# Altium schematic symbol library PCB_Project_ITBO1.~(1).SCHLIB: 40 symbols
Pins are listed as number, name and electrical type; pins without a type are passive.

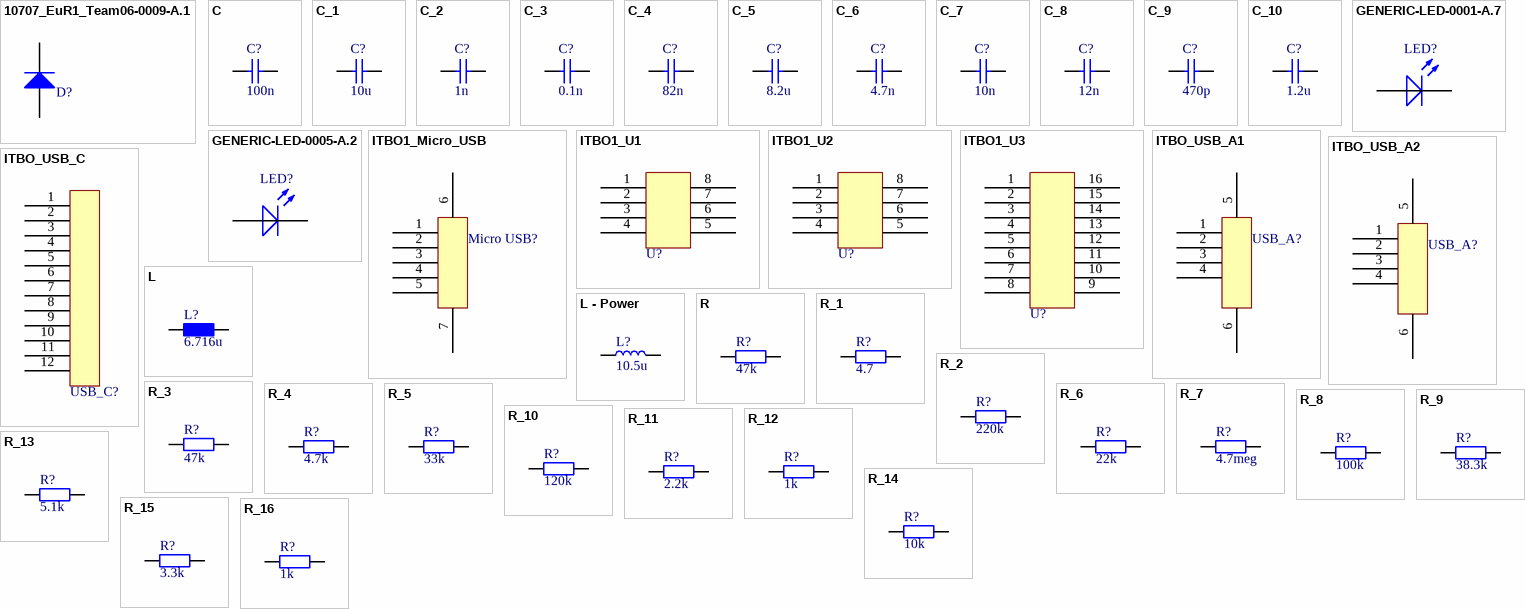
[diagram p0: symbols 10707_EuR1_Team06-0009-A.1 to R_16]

## 10707_EuR1_Team06-0009-A.1
designator D?, comment 1N4148W-7-F  (value not drawn)
Fast Switching Diode, 100 V, 2 A, 300 mA; Manufacturer: Diodes Incorporated
footprint DIODES_SOD123_2_H
pins: 1 K, 2 A

## C
designator C?, comment 100n
Capacitor; #Manufacturer: Generic Components; #Publisher: Dr. A. Heinzelmann; #Class: Passive; Initial Voltage: 0V
footprint 0805
simulation model CAP (Capacitor)
footprint 1210
footprint 0603
footprint CC-Type-B-3528 (Chip Capacitor; Body 3.5 x 2.8 mm (LxW typ))
footprint 1206 (SMD Chip 1206)
footprint 0402 (SMD Chip 0402)
footprint 1812 (Chip Capacitor; Body 4.5 x 3.2 mm (LxW typ))
footprint 0402 - R (SMD Chip 0402 - Reflow)
footprint 0603 - R (SMD Chip 0603 - Reflow)
footprint 0805 - R (SMD Chip 0805 - Reflow)
footprint 1206 - R (SMD Chip 1206 - Reflow)
pins: 1, 2

## C_1
designator C?, comment 10u
Capacitor; #Manufacturer: Generic Components; #Publisher: Dr. A. Heinzelmann; #Class: Passive; Initial Voltage: 0V
footprint 0805
simulation model CAP (Capacitor)
footprint 1210
footprint 0603
footprint CC-Type-B-3528 (Chip Capacitor; Body 3.5 x 2.8 mm (LxW typ))
footprint 1206 (SMD Chip 1206)
footprint 0402 (SMD Chip 0402)
footprint 1812 (Chip Capacitor; Body 4.5 x 3.2 mm (LxW typ))
footprint 0402 - R (SMD Chip 0402 - Reflow)
footprint 0603 - R (SMD Chip 0603 - Reflow)
footprint 0805 - R (SMD Chip 0805 - Reflow)
footprint 1206 - R (SMD Chip 1206 - Reflow)
pins: 1, 2

## C_2
designator C?, comment 1n
Capacitor; #Manufacturer: Generic Components; #Publisher: Dr. A. Heinzelmann; #Class: Passive; Initial Voltage: 0V
footprint 0805
simulation model CAP (Capacitor)
footprint 1210
footprint 0603
footprint CC-Type-B-3528 (Chip Capacitor; Body 3.5 x 2.8 mm (LxW typ))
footprint 1206 (SMD Chip 1206)
footprint 0402 (SMD Chip 0402)
footprint 1812 (Chip Capacitor; Body 4.5 x 3.2 mm (LxW typ))
footprint 0402 - R (SMD Chip 0402 - Reflow)
footprint 0603 - R (SMD Chip 0603 - Reflow)
footprint 0805 - R (SMD Chip 0805 - Reflow)
footprint 1206 - R (SMD Chip 1206 - Reflow)
pins: 1, 2

## C_3
designator C?, comment 0.1n
Capacitor; #Manufacturer: Generic Components; #Publisher: Dr. A. Heinzelmann; #Class: Passive; Initial Voltage: 0V
footprint 0805
simulation model CAP (Capacitor)
footprint 1210
footprint 0603
footprint CC-Type-B-3528 (Chip Capacitor; Body 3.5 x 2.8 mm (LxW typ))
footprint 1206 (SMD Chip 1206)
footprint 0402 (SMD Chip 0402)
footprint 1812 (Chip Capacitor; Body 4.5 x 3.2 mm (LxW typ))
footprint 0402 - R (SMD Chip 0402 - Reflow)
footprint 0603 - R (SMD Chip 0603 - Reflow)
footprint 0805 - R (SMD Chip 0805 - Reflow)
footprint 1206 - R (SMD Chip 1206 - Reflow)
pins: 1, 2

## C_4
designator C?, comment 82n
Capacitor; #Manufacturer: Generic Components; #Publisher: Dr. A. Heinzelmann; #Class: Passive; Initial Voltage: 0V
footprint 0805
simulation model CAP (Capacitor)
footprint 1210
footprint 0603
footprint CC-Type-B-3528 (Chip Capacitor; Body 3.5 x 2.8 mm (LxW typ))
footprint 1206 (SMD Chip 1206)
footprint 0402 (SMD Chip 0402)
footprint 1812 (Chip Capacitor; Body 4.5 x 3.2 mm (LxW typ))
footprint 0402 - R (SMD Chip 0402 - Reflow)
footprint 0603 - R (SMD Chip 0603 - Reflow)
footprint 0805 - R (SMD Chip 0805 - Reflow)
footprint 1206 - R (SMD Chip 1206 - Reflow)
pins: 1, 2

## C_5
designator C?, comment 8.2u
Capacitor; #Manufacturer: Generic Components; #Publisher: Dr. A. Heinzelmann; #Class: Passive; Initial Voltage: 0V
footprint 0805
simulation model CAP (Capacitor)
footprint 1210
footprint 0603
footprint CC-Type-B-3528 (Chip Capacitor; Body 3.5 x 2.8 mm (LxW typ))
footprint 1206 (SMD Chip 1206)
footprint 0402 (SMD Chip 0402)
footprint 1812 (Chip Capacitor; Body 4.5 x 3.2 mm (LxW typ))
footprint 0402 - R (SMD Chip 0402 - Reflow)
footprint 0603 - R (SMD Chip 0603 - Reflow)
footprint 0805 - R (SMD Chip 0805 - Reflow)
footprint 1206 - R (SMD Chip 1206 - Reflow)
pins: 1, 2

## C_6
designator C?, comment 4.7n
Capacitor; #Manufacturer: Generic Components; #Publisher: Dr. A. Heinzelmann; #Class: Passive; Initial Voltage: 0V
footprint 0805
simulation model CAP (Capacitor)
footprint 1210
footprint 0603
footprint CC-Type-B-3528 (Chip Capacitor; Body 3.5 x 2.8 mm (LxW typ))
footprint 1206 (SMD Chip 1206)
footprint 0402 (SMD Chip 0402)
footprint 1812 (Chip Capacitor; Body 4.5 x 3.2 mm (LxW typ))
footprint 0402 - R (SMD Chip 0402 - Reflow)
footprint 0603 - R (SMD Chip 0603 - Reflow)
footprint 0805 - R (SMD Chip 0805 - Reflow)
footprint 1206 - R (SMD Chip 1206 - Reflow)
pins: 1, 2

## C_7
designator C?, comment 10n
Capacitor; #Manufacturer: Generic Components; #Publisher: Dr. A. Heinzelmann; #Class: Passive; Initial Voltage: 0V
footprint 0805
simulation model CAP (Capacitor)
footprint 1210
footprint 0603
footprint CC-Type-B-3528 (Chip Capacitor; Body 3.5 x 2.8 mm (LxW typ))
footprint 1206 (SMD Chip 1206)
footprint 0402 (SMD Chip 0402)
footprint 1812 (Chip Capacitor; Body 4.5 x 3.2 mm (LxW typ))
footprint 0402 - R (SMD Chip 0402 - Reflow)
footprint 0603 - R (SMD Chip 0603 - Reflow)
footprint 0805 - R (SMD Chip 0805 - Reflow)
footprint 1206 - R (SMD Chip 1206 - Reflow)
pins: 1, 2

## C_8
designator C?, comment 12n
Capacitor; #Manufacturer: Generic Components; #Publisher: Dr. A. Heinzelmann; #Class: Passive; Initial Voltage: 0V
footprint 0805
simulation model CAP (Capacitor)
footprint 1210
footprint 0603
footprint CC-Type-B-3528 (Chip Capacitor; Body 3.5 x 2.8 mm (LxW typ))
footprint 1206 (SMD Chip 1206)
footprint 0402 (SMD Chip 0402)
footprint 1812 (Chip Capacitor; Body 4.5 x 3.2 mm (LxW typ))
footprint 0402 - R (SMD Chip 0402 - Reflow)
footprint 0603 - R (SMD Chip 0603 - Reflow)
footprint 0805 - R (SMD Chip 0805 - Reflow)
footprint 1206 - R (SMD Chip 1206 - Reflow)
pins: 1, 2

## C_9
designator C?, comment 470p
Capacitor; #Manufacturer: Generic Components; #Publisher: Dr. A. Heinzelmann; #Class: Passive; Initial Voltage: 0V
footprint 0805
simulation model CAP (Capacitor)
footprint 1210
footprint 0603
footprint CC-Type-B-3528 (Chip Capacitor; Body 3.5 x 2.8 mm (LxW typ))
footprint 1206 (SMD Chip 1206)
footprint 0402 (SMD Chip 0402)
footprint 1812 (Chip Capacitor; Body 4.5 x 3.2 mm (LxW typ))
footprint 0402 - R (SMD Chip 0402 - Reflow)
footprint 0603 - R (SMD Chip 0603 - Reflow)
footprint 0805 - R (SMD Chip 0805 - Reflow)
footprint 1206 - R (SMD Chip 1206 - Reflow)
pins: 1, 2

## C_10
designator C?, comment 1.2u
Capacitor; #Manufacturer: Generic Components; #Publisher: Dr. A. Heinzelmann; #Class: Passive; Initial Voltage: 0V
footprint 0805
simulation model CAP (Capacitor)
footprint 1210
footprint 0603
footprint CC-Type-B-3528 (Chip Capacitor; Body 3.5 x 2.8 mm (LxW typ))
footprint 1206 (SMD Chip 1206)
footprint 0402 (SMD Chip 0402)
footprint 1812 (Chip Capacitor; Body 4.5 x 3.2 mm (LxW typ))
footprint 0402 - R (SMD Chip 0402 - Reflow)
footprint 0603 - R (SMD Chip 0603 - Reflow)
footprint 0805 - R (SMD Chip 0805 - Reflow)
footprint 1206 - R (SMD Chip 1206 - Reflow)
pins: 1, 2

## GENERIC-LED-0001-A.7
designator LED?, comment tbd  (value not drawn)
LED red; Manufacturer: generic; #ClassSub: LEDs; #Class: Generic-Components
footprint LED-RED-0603[1608]  - RFL (SMD Chip 0603 - LED RED - RFL)
footprint LED-RED-0603[1608] (SMD Chip 0603 - LED RED)
footprint LED-RED-0805[2012] (SMD Chip 0805 - LED RED)
footprint LED-RED-0805[2012]  - RFL (SMD Chip 0805 - LED RED - RFL)
pins: 1 K, 2 A

## GENERIC-LED-0005-A.2
designator LED?, comment tbd  (value not drawn)
LED blue; Manufacturer: generic; #ClassSub: LEDs; #Class: Generic-Components
footprint LED-BLUE-0603[1608]  - RFL (SMD Chip 0603 - LED BLUE - RFL)
footprint LED-BLUE-0805[2012]  - RFL (SMD Chip 0805 - LED BLUE - RFL)
footprint LED-BLUE-0805[2012] (SMD Chip 0805 - LED BLUE)
footprint LED-BLUE-0603[1608] (SMD Chip 0603 - LED BLUE)
pins: 1 K, 2 A

## ITBO1_Micro_USB
designator Micro USB?  (value not drawn)
footprint MOLEX_1051330001
pins: 1, 2, 3, 4, 5, 6, 7

## ITBO1_U1
designator U?  (value not drawn)
footprint ITBO1_U1 (TSOP, 8-Leads, Body 4.85x3.85mm, Pitch 1.27mm, IPC Medium Density)
pins: 1, 2, 3, 4, 5, 6, 7, 8

## ITBO1_U2
designator U?  (value not drawn)
footprint ITBO1_U2 (TSOP, 8-Leads, Body 4.85x3.85mm, Pitch 1.27mm, IPC Medium Density)
pins: 1, 2, 3, 4, 5, 6, 7, 8

## ITBO1_U3
designator U?  (value not drawn)
footprint ITBO1_U3
pins: 1, 2, 3, 4, 5, 6, 7, 8, 9, 10, 11, 12, 13, 14, 15, 16

## ITBO_USB_A1
designator USB_A?  (value not drawn)
footprint MOLEX_48037-0001
pins: 1, 2, 3, 4, 5, 6

## ITBO_USB_A2
designator USB_A?  (value not drawn)
footprint MOLEX_48037-0001
pins: 1, 2, 3, 4, 5, 6

## ITBO_USB_C
designator USB_C?  (value not drawn)
footprint MOLEX_105450-0101
pins: 1, 2, 3, 4, 5, 6, 7, 8, 9, 10, 11, 12

## L
designator L?  value 6.716u  (hidden comment: L)
Inductor; #Manufacturer: Generic Components; #Publisher: Dr. A. Heinzelmann; #Class: Passive; #ClassSub: Resistor
simulation model Inductor (ideal Inductor)
footprint 0805 (SMD Chip 0805)
footprint 1206 (SMD Chip 1206)
footprint 0603 (SMD Chip 0603)
footprint 0402 (SMD Chip 0402)
footprint 1210 (SMD Chip 1210)
footprint 0402 - R (SMD Chip 0402 - Reflow)
footprint 0805 - R (SMD Chip 0805 - Reflow)
footprint 0603 - R (SMD Chip 0603 - Reflow)
footprint SRR1240 (Footprint not found)
footprint 1806 - R (Body 5 x 2 mm (LxW typ))
footprint WE-PD (Power Choke WE-PD)
pins: 1, 2

## L - Power
designator L?, comment 10.5u
Inductor - Power; #Manufacturer: Generic Components; #Publisher: Dr. A. Heinzelmann; #Class: Passive; #ClassSub: Resistor
simulation model Inductor (ideal Inductor)
footprint WE-TPC (Power-Choke WE-TPC 2.8 x 2.8)
pins: 1, 2

## R
designator R?, comment 47k
Resistor; #Manufacturer: Generic Components; #Publisher: Dr. A. Heinzelmann; #Class: Passive
simulation model RESISTOR (Resistor (Standard))
footprint 0805 (SMD Chip 0805)
footprint 1206 (SMD Chip 1206)
footprint 0603 (SMD Chip 0603)
footprint 0402 (SMD Chip 0402)
footprint 0402 - R (SMD Chip 0402 - Reflow)
footprint 1206 - R (SMD Chip 1206 - Reflow)
footprint 0603 - R (SMD Chip 0603 - Reflow)
footprint 0805 - R (SMD Chip 0805 - Reflow)
footprint 2512[6332] (SMD Chip 250 x 120 mil or 6.3 x 3.2 mm)
footprint 2010[5025] (SMD Chip 200 x 100 mil or 5.0 x 2.5 mm)
footprint 02016 (SMD Chip 02016)
footprint AXIAL-0.4 (Resistor; 2 Leads)
pins: 1, 2

## R_1
designator R?, comment 4.7
Resistor; #Manufacturer: Generic Components; #Publisher: Dr. A. Heinzelmann; #Class: Passive
simulation model RESISTOR (Resistor (Standard))
footprint 0805 (SMD Chip 0805)
footprint 1206 (SMD Chip 1206)
footprint 0603 (SMD Chip 0603)
footprint 0402 (SMD Chip 0402)
footprint 0402 - R (SMD Chip 0402 - Reflow)
footprint 1206 - R (SMD Chip 1206 - Reflow)
footprint 0603 - R (SMD Chip 0603 - Reflow)
footprint 0805 - R (SMD Chip 0805 - Reflow)
footprint 2512[6332] (SMD Chip 250 x 120 mil or 6.3 x 3.2 mm)
footprint 2010[5025] (SMD Chip 200 x 100 mil or 5.0 x 2.5 mm)
footprint 02016 (SMD Chip 02016)
footprint AXIAL-0.4 (Resistor; 2 Leads)
pins: 1, 2

## R_2
designator R?, comment 220k
Resistor; #Manufacturer: Generic Components; #Publisher: Dr. A. Heinzelmann; #Class: Passive
simulation model RESISTOR (Resistor (Standard))
footprint 0805 (SMD Chip 0805)
footprint 1206 (SMD Chip 1206)
footprint 0603 (SMD Chip 0603)
footprint 0402 (SMD Chip 0402)
footprint 0402 - R (SMD Chip 0402 - Reflow)
footprint 1206 - R (SMD Chip 1206 - Reflow)
footprint 0603 - R (SMD Chip 0603 - Reflow)
footprint 0805 - R (SMD Chip 0805 - Reflow)
footprint 2512[6332] (SMD Chip 250 x 120 mil or 6.3 x 3.2 mm)
footprint 2010[5025] (SMD Chip 200 x 100 mil or 5.0 x 2.5 mm)
footprint 02016 (SMD Chip 02016)
footprint AXIAL-0.4 (Resistor; 2 Leads)
pins: 1, 2

## R_3
designator R?, comment 47k
Resistor; #Manufacturer: Generic Components; #Publisher: Dr. A. Heinzelmann; #Class: Passive
simulation model RESISTOR (Resistor (Standard))
footprint 0805 (SMD Chip 0805)
footprint 1206 (SMD Chip 1206)
footprint 0603 (SMD Chip 0603)
footprint 0402 (SMD Chip 0402)
footprint 0402 - R (SMD Chip 0402 - Reflow)
footprint 1206 - R (SMD Chip 1206 - Reflow)
footprint 0603 - R (SMD Chip 0603 - Reflow)
footprint 0805 - R (SMD Chip 0805 - Reflow)
footprint 2512[6332] (SMD Chip 250 x 120 mil or 6.3 x 3.2 mm)
footprint 2010[5025] (SMD Chip 200 x 100 mil or 5.0 x 2.5 mm)
footprint 02016 (SMD Chip 02016)
footprint AXIAL-0.4 (Resistor; 2 Leads)
pins: 1, 2

## R_4
designator R?, comment 4.7k
Resistor; #Manufacturer: Generic Components; #Publisher: Dr. A. Heinzelmann; #Class: Passive
simulation model RESISTOR (Resistor (Standard))
footprint 0805 (SMD Chip 0805)
footprint 1206 (SMD Chip 1206)
footprint 0603 (SMD Chip 0603)
footprint 0402 (SMD Chip 0402)
footprint 0402 - R (SMD Chip 0402 - Reflow)
footprint 1206 - R (SMD Chip 1206 - Reflow)
footprint 0603 - R (SMD Chip 0603 - Reflow)
footprint 0805 - R (SMD Chip 0805 - Reflow)
footprint 2512[6332] (SMD Chip 250 x 120 mil or 6.3 x 3.2 mm)
footprint 2010[5025] (SMD Chip 200 x 100 mil or 5.0 x 2.5 mm)
footprint 02016 (SMD Chip 02016)
footprint AXIAL-0.4 (Resistor; 2 Leads)
pins: 1, 2

## R_5
designator R?, comment 33k
Resistor; #Manufacturer: Generic Components; #Publisher: Dr. A. Heinzelmann; #Class: Passive
simulation model RESISTOR (Resistor (Standard))
footprint 0805 (SMD Chip 0805)
footprint 1206 (SMD Chip 1206)
footprint 0603 (SMD Chip 0603)
footprint 0402 (SMD Chip 0402)
footprint 0402 - R (SMD Chip 0402 - Reflow)
footprint 1206 - R (SMD Chip 1206 - Reflow)
footprint 0603 - R (SMD Chip 0603 - Reflow)
footprint 0805 - R (SMD Chip 0805 - Reflow)
footprint 2512[6332] (SMD Chip 250 x 120 mil or 6.3 x 3.2 mm)
footprint 2010[5025] (SMD Chip 200 x 100 mil or 5.0 x 2.5 mm)
footprint 02016 (SMD Chip 02016)
footprint AXIAL-0.4 (Resistor; 2 Leads)
pins: 1, 2

## R_6
designator R?, comment 22k
Resistor; #Manufacturer: Generic Components; #Publisher: Dr. A. Heinzelmann; #Class: Passive
simulation model RESISTOR (Resistor (Standard))
footprint 0805 (SMD Chip 0805)
footprint 1206 (SMD Chip 1206)
footprint 0603 (SMD Chip 0603)
footprint 0402 (SMD Chip 0402)
footprint 0402 - R (SMD Chip 0402 - Reflow)
footprint 1206 - R (SMD Chip 1206 - Reflow)
footprint 0603 - R (SMD Chip 0603 - Reflow)
footprint 0805 - R (SMD Chip 0805 - Reflow)
footprint 2512[6332] (SMD Chip 250 x 120 mil or 6.3 x 3.2 mm)
footprint 2010[5025] (SMD Chip 200 x 100 mil or 5.0 x 2.5 mm)
footprint 02016 (SMD Chip 02016)
footprint AXIAL-0.4 (Resistor; 2 Leads)
pins: 1, 2

## R_7
designator R?, comment 4.7meg
Resistor; #Manufacturer: Generic Components; #Publisher: Dr. A. Heinzelmann; #Class: Passive
simulation model RESISTOR (Resistor (Standard))
footprint 0805 (SMD Chip 0805)
footprint 1206 (SMD Chip 1206)
footprint 0603 (SMD Chip 0603)
footprint 0402 (SMD Chip 0402)
footprint 0402 - R (SMD Chip 0402 - Reflow)
footprint 1206 - R (SMD Chip 1206 - Reflow)
footprint 0603 - R (SMD Chip 0603 - Reflow)
footprint 0805 - R (SMD Chip 0805 - Reflow)
footprint 2512[6332] (SMD Chip 250 x 120 mil or 6.3 x 3.2 mm)
footprint 2010[5025] (SMD Chip 200 x 100 mil or 5.0 x 2.5 mm)
footprint 02016 (SMD Chip 02016)
footprint AXIAL-0.4 (Resistor; 2 Leads)
pins: 1, 2

## R_8
designator R?, comment 100k
Resistor; #Manufacturer: Generic Components; #Publisher: Dr. A. Heinzelmann; #Class: Passive
simulation model RESISTOR (Resistor (Standard))
footprint 0805 (SMD Chip 0805)
footprint 1206 (SMD Chip 1206)
footprint 0603 (SMD Chip 0603)
footprint 0402 (SMD Chip 0402)
footprint 0402 - R (SMD Chip 0402 - Reflow)
footprint 1206 - R (SMD Chip 1206 - Reflow)
footprint 0603 - R (SMD Chip 0603 - Reflow)
footprint 0805 - R (SMD Chip 0805 - Reflow)
footprint 2512[6332] (SMD Chip 250 x 120 mil or 6.3 x 3.2 mm)
footprint 2010[5025] (SMD Chip 200 x 100 mil or 5.0 x 2.5 mm)
footprint 02016 (SMD Chip 02016)
footprint AXIAL-0.4 (Resistor; 2 Leads)
pins: 1, 2

## R_9
designator R?, comment 38.3k
Resistor; #Manufacturer: Generic Components; #Publisher: Dr. A. Heinzelmann; #Class: Passive
simulation model RESISTOR (Resistor (Standard))
footprint 0805 (SMD Chip 0805)
footprint 1206 (SMD Chip 1206)
footprint 0603 (SMD Chip 0603)
footprint 0402 (SMD Chip 0402)
footprint 0402 - R (SMD Chip 0402 - Reflow)
footprint 1206 - R (SMD Chip 1206 - Reflow)
footprint 0603 - R (SMD Chip 0603 - Reflow)
footprint 0805 - R (SMD Chip 0805 - Reflow)
footprint 2512[6332] (SMD Chip 250 x 120 mil or 6.3 x 3.2 mm)
footprint 2010[5025] (SMD Chip 200 x 100 mil or 5.0 x 2.5 mm)
footprint 02016 (SMD Chip 02016)
footprint AXIAL-0.4 (Resistor; 2 Leads)
pins: 1, 2

## R_10
designator R?, comment 120k
Resistor; #Manufacturer: Generic Components; #Publisher: Dr. A. Heinzelmann; #Class: Passive
simulation model RESISTOR (Resistor (Standard))
footprint 0805 (SMD Chip 0805)
footprint 1206 (SMD Chip 1206)
footprint 0603 (SMD Chip 0603)
footprint 0402 (SMD Chip 0402)
footprint 0402 - R (SMD Chip 0402 - Reflow)
footprint 1206 - R (SMD Chip 1206 - Reflow)
footprint 0603 - R (SMD Chip 0603 - Reflow)
footprint 0805 - R (SMD Chip 0805 - Reflow)
footprint 2512[6332] (SMD Chip 250 x 120 mil or 6.3 x 3.2 mm)
footprint 2010[5025] (SMD Chip 200 x 100 mil or 5.0 x 2.5 mm)
footprint 02016 (SMD Chip 02016)
footprint AXIAL-0.4 (Resistor; 2 Leads)
pins: 1, 2

## R_11
designator R?, comment 2.2k
Resistor; #Manufacturer: Generic Components; #Publisher: Dr. A. Heinzelmann; #Class: Passive
simulation model RESISTOR (Resistor (Standard))
footprint 0805 (SMD Chip 0805)
footprint 1206 (SMD Chip 1206)
footprint 0603 (SMD Chip 0603)
footprint 0402 (SMD Chip 0402)
footprint 0402 - R (SMD Chip 0402 - Reflow)
footprint 1206 - R (SMD Chip 1206 - Reflow)
footprint 0603 - R (SMD Chip 0603 - Reflow)
footprint 0805 - R (SMD Chip 0805 - Reflow)
footprint 2512[6332] (SMD Chip 250 x 120 mil or 6.3 x 3.2 mm)
footprint 2010[5025] (SMD Chip 200 x 100 mil or 5.0 x 2.5 mm)
footprint 02016 (SMD Chip 02016)
footprint AXIAL-0.4 (Resistor; 2 Leads)
pins: 1, 2

## R_12
designator R?, comment 1k
Resistor; #Manufacturer: Generic Components; #Publisher: Dr. A. Heinzelmann; #Class: Passive
simulation model RESISTOR (Resistor (Standard))
footprint 0805 (SMD Chip 0805)
footprint 1206 (SMD Chip 1206)
footprint 0603 (SMD Chip 0603)
footprint 0402 (SMD Chip 0402)
footprint 0402 - R (SMD Chip 0402 - Reflow)
footprint 1206 - R (SMD Chip 1206 - Reflow)
footprint 0603 - R (SMD Chip 0603 - Reflow)
footprint 0805 - R (SMD Chip 0805 - Reflow)
footprint 2512[6332] (SMD Chip 250 x 120 mil or 6.3 x 3.2 mm)
footprint 2010[5025] (SMD Chip 200 x 100 mil or 5.0 x 2.5 mm)
footprint 02016 (SMD Chip 02016)
footprint AXIAL-0.4 (Resistor; 2 Leads)
pins: 1, 2

## R_13
designator R?, comment 5.1k
Resistor; #Manufacturer: Generic Components; #Publisher: Dr. A. Heinzelmann; #Class: Passive
simulation model RESISTOR (Resistor (Standard))
footprint 0805 (SMD Chip 0805)
footprint 1206 (SMD Chip 1206)
footprint 0603 (SMD Chip 0603)
footprint 0402 (SMD Chip 0402)
footprint 0402 - R (SMD Chip 0402 - Reflow)
footprint 1206 - R (SMD Chip 1206 - Reflow)
footprint 0603 - R (SMD Chip 0603 - Reflow)
footprint 0805 - R (SMD Chip 0805 - Reflow)
footprint 2512[6332] (SMD Chip 250 x 120 mil or 6.3 x 3.2 mm)
footprint 2010[5025] (SMD Chip 200 x 100 mil or 5.0 x 2.5 mm)
footprint 02016 (SMD Chip 02016)
footprint AXIAL-0.4 (Resistor; 2 Leads)
pins: 1, 2

## R_14
designator R?, comment 10k
Resistor; #Manufacturer: Generic Components; #Publisher: Dr. A. Heinzelmann; #Class: Passive
simulation model RESISTOR (Resistor (Standard))
footprint 0805 (SMD Chip 0805)
footprint 1206 (SMD Chip 1206)
footprint 0603 (SMD Chip 0603)
footprint 0402 (SMD Chip 0402)
footprint 0402 - R (SMD Chip 0402 - Reflow)
footprint 1206 - R (SMD Chip 1206 - Reflow)
footprint 0603 - R (SMD Chip 0603 - Reflow)
footprint 0805 - R (SMD Chip 0805 - Reflow)
footprint 2512[6332] (SMD Chip 250 x 120 mil or 6.3 x 3.2 mm)
footprint 2010[5025] (SMD Chip 200 x 100 mil or 5.0 x 2.5 mm)
footprint 02016 (SMD Chip 02016)
footprint AXIAL-0.4 (Resistor; 2 Leads)
pins: 1, 2

## R_15
designator R?, comment 3.3k
Resistor; #Manufacturer: Generic Components; #Publisher: Dr. A. Heinzelmann; #Class: Passive
simulation model RESISTOR (Resistor (Standard))
footprint 0805 (SMD Chip 0805)
footprint 1206 (SMD Chip 1206)
footprint 0603 (SMD Chip 0603)
footprint 0402 (SMD Chip 0402)
footprint 0402 - R (SMD Chip 0402 - Reflow)
footprint 1206 - R (SMD Chip 1206 - Reflow)
footprint 0603 - R (SMD Chip 0603 - Reflow)
footprint 0805 - R (SMD Chip 0805 - Reflow)
footprint 2512[6332] (SMD Chip 250 x 120 mil or 6.3 x 3.2 mm)
footprint 2010[5025] (SMD Chip 200 x 100 mil or 5.0 x 2.5 mm)
footprint 02016 (SMD Chip 02016)
footprint AXIAL-0.4 (Resistor; 2 Leads)
pins: 1, 2

## R_16
designator R?, comment value 1k  (hidden comment: 4.7)
Resistor; #Manufacturer: Generic Components; #Publisher: Dr. A. Heinzelmann; #Class: Passive
simulation model RESISTOR (Resistor (Standard))
footprint 0805 (SMD Chip 0805)
footprint 1206 (SMD Chip 1206)
footprint 0603 (SMD Chip 0603)
footprint 0402 (SMD Chip 0402)
footprint 0402 - R (SMD Chip 0402 - Reflow)
footprint 1206 - R (SMD Chip 1206 - Reflow)
footprint 0603 - R (SMD Chip 0603 - Reflow)
footprint 0805 - R (SMD Chip 0805 - Reflow)
footprint 2512[6332] (SMD Chip 250 x 120 mil or 6.3 x 3.2 mm)
footprint 2010[5025] (SMD Chip 200 x 100 mil or 5.0 x 2.5 mm)
footprint 02016 (SMD Chip 02016)
footprint AXIAL-0.4 (Resistor; 2 Leads)
pins: 1, 2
